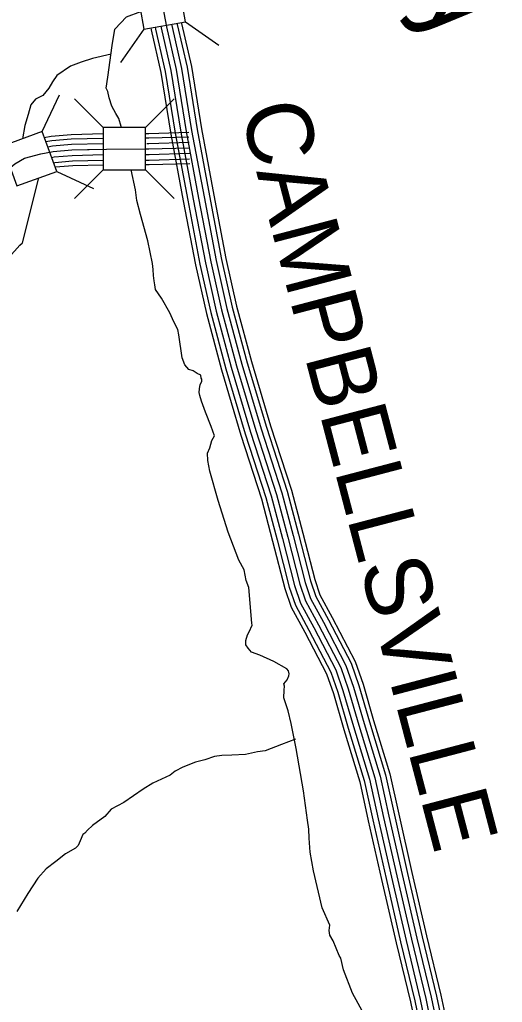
# Model space of a CAD drawing. Extents: x 1551132 to 1791609, y 378168 to 563823.
# Drawn here: x 1640452 to 1643158, y 410247 to 415751 of the extents above; entities that cross this region are included whole.
import ezdxf

# ---------------------------------------------------------------- set-up
doc = ezdxf.new("R2010")
doc.units = 0
for name, color, linetype in [('DESIGN - DRAINAGE - Bridges and Cross Drains Size Text', 7, 'Continuous'), ('DESIGN - ROW - Right-of-Way and Easement Labels', 7, 'Continuous'), ('DESIGN - TRANSPORTATION - Text', 7, 'Continuous'), ('SURVEY - CONTROL with Text', 7, 'Continuous'), ('SURVEY - DRAINAGE - Storm Sewer', 7, 'Continuous'), ('SURVEY - PROPERTY - Owners', 7, 'Continuous'), ('SURVEY - TRANSPORTATION - Roads', 7, 'Continuous')]:
    doc.layers.add(name, color=color, linetype=linetype)

msp = doc.modelspace()

# ---------------------------------------------------------------- linework, layer by layer
at = {"layer": 'DESIGN - TRANSPORTATION - Text'}
for points in [[(1641023.022, 415147.463), (1641021.68, 415152.822), (1641007.972, 415196.99), (1640990.156, 415225.165), (1640968.432, 415267.383), (1640952.74, 415313.568), (1640946.974, 415349.669), (1640937.091, 415367.769), (1640945.499, 415429.812), (1640970.665, 415605.859), (1640985.34, 415698.794), (1641051.355, 415767.28), (1641130.428, 415797.93)], [(1640963.965, 415558.999), (1640860.643, 415534.632), (1640797.069, 415512.623), (1640735.945, 415490.614), (1640660.147, 415439.254), (1640635.698, 415402.561), (1640616.14, 415368.327), (1640581.907, 415326.743), (1640541.558, 415305.351), (1640514.667, 415274.775), (1640498.768, 415219.748), (1640480.435, 415158.605), (1640466.993, 415083.995)], [(1641736.754, 412571.563), (1641721.004, 412609.73), (1641709.396, 412669.915), (1641679.755, 412724.208), (1641620.782, 412880.887), (1641563.941, 413057.575), (1641517.018, 413222.171), (1641507.418, 413282.34), (1641505.676, 413322.416), (1641517.876, 413352.375), (1641528.151, 413394.376), (1641544.317, 413420.302), (1641524.659, 413472.528), (1641493.185, 413552.88), (1641471.594, 413615.132), (1641461.794, 413645.249), (1641457.911, 413663.308), (1641460.044, 413683.325), (1641464.202, 413707.334), (1641472.319, 413725.31), (1641472.394, 413737.326), (1641468.436, 413743.368), (1641466.544, 413759.402), (1641446.611, 413769.561), (1641424.703, 413783.744), (1641400.754, 413791.92), (1641388.838, 413804.028), (1641376.93, 413818.137), (1641363.18, 413856.296), (1641344.03, 413986.641), (1641338.231, 414016.734), (1641316.506, 414058.952), (1641292.84, 414109.203), (1641247.383, 414191.663), (1641213.7, 414239.973), (1641209.867, 414266.049), (1641206.009, 414288.108), (1641202.209, 414318.183), (1641200.434, 414352.251), (1641196.659, 414386.335), (1641169.485, 414512.73), (1641128.444, 414659.259), (1641108.961, 414737.528), (1641101.353, 414797.679), (1641077.462, 414909.799)], [(1640344.571, 414366.659), (1640453.368, 414488.087), (1640467.726, 414501.746), (1640559.258, 414864.739)], [(1642392.262, 410162.866), (1642317.147, 410297.62), (1642267.998, 410428.182), (1642252.441, 410494.4), (1642242.532, 410508.492), (1642209.067, 410590.861), (1642191.284, 410623.037), (1642187.45, 410649.112), (1642189.65, 410679.146), (1642148.285, 410775.591), (1642099.653, 410984.279), (1642080.337, 411088.582), (1642074.845, 411166.751), (1642073.17, 411216.844), (1642065.504, 411266.979), (1642042.579, 411431.408), (1642002.13, 411668.081), (1641973.056, 411808.518), (1641957.523, 411880.745), (1641931.999, 411953.038), (1641934.274, 411995.089), (1641936.424, 412017.115), (1641932.516, 412031.165), (1641950.657, 412053.074), (1641960.798, 412075.033), (1641962.873, 412087.042), (1641958.982, 412103.092), (1641949.065, 412115.184), (1641877.334, 412155.76), (1641797.577, 412192.378), (1641751.678, 412208.728), (1641731.829, 412230.912), (1641719.946, 412249.021), (1641720.104, 412273.063), (1641728.312, 412305.056), (1641738.429, 412323.014), (1641754.662, 412358.957), (1641752.945, 412371.624), (1641736.754, 412571.563)], [(1641998.855, 411720.199), (1641918.974, 411690.84), (1641828.751, 411655.414), (1641784.71, 411649.722), (1641718.629, 411636.163), (1641640.589, 411630.713), (1641584.582, 411629.104), (1641544.549, 411623.379), (1641490.434, 411605.729), (1641438.344, 411592.078), (1641366.17, 411564.544), (1641324.03, 411542.81), (1641295.872, 411518.968), (1641197.591, 411475.592), (1641143.375, 411441.924), (1641034.886, 411366.564), (1640964.638, 411329.005), (1640928.364, 411287.195), (1640860.049, 411237.594), (1640831.874, 411211.751), (1640817.758, 411193.826), (1640805.725, 411187.901), (1640791.483, 411151.941), (1640779.317, 411125.982), (1640765.217, 411110.057), (1640709.01, 411078.406), (1640654.737, 411036.722), (1640600.463, 410995.037), (1640554.131, 410943.277), (1640497.565, 410857.542), (1640436.908, 410755.806)]]:
    msp.add_lwpolyline(points, dxfattribs=at)
at = {"layer": 'SURVEY - CONTROL with Text'}
for points in [[(1641235.834, 415918.325), (1641274.641, 415711.637), (1641329.282, 415472.772), (1641385.263, 415125.663), (1641455.112, 414752.412), (1641523.06, 414395.21), (1641583.525, 414126.245), (1641667.756, 413813.037), (1641775.72, 413449.586), (1641891.734, 413092.085), (1641954.382, 412853.179), (1642022.897, 412590.18), (1642054.371, 412495.786), (1642127.669, 412361.041), (1642252.408, 412121.759), (1642293.757, 412003.248), (1642352.622, 411800.443), (1642442.97, 411505.243), (1642491.702, 411282.454), (1642565.833, 410955.279), (1642647.806, 410599.995), (1642727.929, 410268.778), (1642766.853, 410082.123)], [(1641186.652, 415704.936), (1641188.752, 415693.753), (1641243.142, 415455.988), (1641298.84, 415110.613), (1641368.922, 414736.144), (1641437.162, 414377.385), (1641498.344, 414105.228), (1641583.35, 413789.153), (1641691.947, 413423.552), (1641807.527, 413067.401), (1641869.517, 412830.995), (1641938.757, 412565.221), (1641973.615, 412460.677), (1642050.246, 412319.806), (1642171.685, 412086.85), (1642210.167, 411976.556), (1642268.566, 411775.375), (1642358.047, 411483.001), (1642406.087, 411263.387), (1642480.327, 410935.728), (1642562.442, 410579.819), (1642642.348, 410249.502), (1642681.73, 410060.647)], [(1641211.968, 415709.445), (1641213.934, 415698.995), (1641268.391, 415460.913), (1641324.181, 415115.021), (1641394.188, 414740.911), (1641462.345, 414382.61), (1641523.318, 414111.386), (1641608.091, 413796.153), (1641716.513, 413431.185), (1641832.21, 413074.634), (1641894.4, 412837.503), (1641963.423, 412572.538), (1641997.289, 412470.968), (1642072.946, 412331.89), (1642195.351, 412097.084), (1642234.675, 411984.381), (1642293.207, 411782.726), (1642382.946, 411489.518), (1642431.187, 411268.979), (1642505.393, 410941.462), (1642587.466, 410585.736), (1642667.439, 410255.152), (1642706.688, 410066.939)], [(1641242.5, 415714.812), (1641244.284, 415705.32), (1641298.841, 415466.839), (1641354.722, 415120.346), (1641424.654, 414746.661), (1641492.702, 414388.91), (1641553.426, 414118.82), (1641637.923, 413804.595), (1641746.112, 413440.386), (1641861.976, 413083.36), (1641924.391, 412845.337), (1641993.164, 412581.363), (1642025.83, 412483.377), (1642100.312, 412346.465), (1642223.884, 412109.426), (1642264.216, 411993.814), (1642322.915, 411791.584), (1642412.954, 411497.385), (1642461.444, 411275.712), (1642535.617, 410948.37), (1642617.64, 410592.861), (1642697.68, 410261.969), (1642736.771, 410074.531)], [(1641273.033, 415720.212), (1641274.641, 415711.637), (1641329.282, 415472.772), (1641385.263, 415125.663), (1641455.112, 414752.412), (1641523.06, 414395.21), (1641583.525, 414126.245), (1641667.756, 413813.037), (1641775.72, 413449.586), (1641891.734, 413092.085), (1641954.382, 412853.179), (1642022.897, 412590.18), (1642054.371, 412495.786), (1642127.669, 412361.041), (1642252.408, 412121.759), (1642293.757, 412003.248), (1642352.622, 411800.443), (1642442.97, 411505.243), (1642491.702, 411282.454), (1642565.833, 410955.279), (1642647.806, 410599.995), (1642727.929, 410268.778), (1642766.853, 410082.123)], [(1641303.557, 415725.629), (1641304.999, 415717.953), (1641359.723, 415478.706), (1641415.804, 415130.98), (1641485.569, 414758.162), (1641553.417, 414401.511), (1641613.624, 414133.67), (1641697.589, 413821.479), (1641805.328, 413458.786), (1641921.491, 413100.81), (1641984.373, 412861.02), (1642052.63, 412598.997), (1642082.912, 412508.195), (1642155.027, 412375.616), (1642280.932, 412134.093), (1642323.298, 412012.682), (1642382.33, 411809.301), (1642472.986, 411513.102), (1642521.96, 411289.196), (1642596.049, 410962.187), (1642677.972, 410607.128), (1642758.179, 410275.586), (1642796.936, 410089.715)], [(1641334.09, 415730.962), (1641335.348, 415724.279), (1641390.172, 415484.631), (1641446.345, 415136.305), (1641516.035, 414763.912), (1641583.775, 414407.811), (1641643.732, 414141.104), (1641727.421, 413829.921), (1641834.927, 413467.986), (1641951.257, 413109.535), (1642014.364, 412868.854), (1642082.371, 412607.822), (1642111.453, 412520.603), (1642182.393, 412390.191), (1642309.465, 412146.435), (1642352.839, 412022.115), (1642412.038, 411818.16), (1642502.994, 411520.969), (1642552.217, 411295.93), (1642626.274, 410969.096), (1642708.147, 410614.253), (1642788.42, 410282.403), (1642827.019, 410097.306)], [(1641358.431, 415735.296), (1641359.556, 415729.312), (1641414.438, 415489.364), (1641470.695, 415140.547), (1641540.326, 414768.487), (1641607.974, 414412.828), (1641667.731, 414147.029), (1641751.204, 413836.646), (1641858.535, 413475.32), (1641974.982, 413116.485), (1642038.28, 412875.112), (1642106.078, 412614.856), (1642134.211, 412530.495), (1642204.209, 412401.808), (1642332.206, 412156.269), (1642376.388, 412029.64), (1642435.72, 411825.218), (1642526.926, 411527.236), (1642576.342, 411301.305), (1642650.365, 410974.613), (1642732.196, 410619.937), (1642812.536, 410287.828), (1642851.001, 410103.357)]]:
    msp.add_lwpolyline(points, dxfattribs=at)
at = {"layer": 'SURVEY - DRAINAGE - Storm Sewer'}
for p, q in [((1641381.961, 415739.435), (1641568.007, 415609.164)), ((1641148.02, 415698.179), (1641017.758, 415512.125)), ((1640578.53, 415124.585), (1640674.517, 415330.447)), ((1640919.885, 415147.816), (1640759.28, 415308.412)), ((1641157.477, 415147.822), (1641318.073, 415308.434)), ((1640659.761, 414901.312), (1640865.605, 414805.325)), ((1640919.891, 414910.232), (1640759.286, 414749.619)), ((1641157.441, 414910.238), (1641318.046, 414749.641))]:
    msp.add_line(p, q, dxfattribs=at)
for points in [[(1641148.02, 415698.179), (1641382.003, 415739.435), (1641340.739, 415973.417), (1641106.756, 415932.162)], [(1640436.529, 414820.073), (1640659.803, 414901.337), (1640578.53, 415124.585), (1640355.265, 415043.33)], [(1640919.891, 414910.232), (1641157.483, 414910.238), (1641157.477, 415147.822), (1640919.885, 415147.816)]]:
    msp.add_lwpolyline(points, close=True, dxfattribs=at)
at = {"layer": 'SURVEY - PROPERTY - Owners'}
msp.add_lwpolyline([(1639573.914, 414056.642), (1639626.487, 414119.694), (1639888.506, 414412.06), (1640021.603, 414571.239), (1640106.168, 414652.7), (1640200.849, 414752.102), (1640319.572, 414857.322), (1640424.169, 414944.633), (1640478.385, 414976.259), (1640570.532, 414999.584), (1640640.606, 415013.068), (1640744.653, 415022.285), (1640938.64, 415026.802), (1641176.593, 415026.985), (1641402.446, 415033.861)], dxfattribs=at)
at = {"layer": 'SURVEY - TRANSPORTATION - Roads'}
for points in [[(1640590.157, 415091.67), (1640628.556, 415099.062), (1640739.812, 415108.912), (1640919.866, 415113.104)], [(1641157.477, 415113.688), (1641175.243, 415113.704), (1641399.805, 415120.538)], [(1641157.477, 415088.97), (1641175.627, 415088.987), (1641400.563, 415095.837)], [(1640598.873, 415068.178), (1640631.989, 415074.553), (1640741.195, 415084.22), (1640919.883, 415088.387)], [(1640609.69, 415038.694), (1640636.298, 415043.81), (1640742.92, 415053.252), (1640919.866, 415057.378)], [(1641165.085, 415057.978), (1641176.11, 415057.986), (1641401.505, 415064.845)], [(1640620.348, 415009.168), (1640640.606, 415013.068), (1640744.653, 415022.285), (1640920.008, 415026.368)], [(1640631.139, 414979.675), (1640644.914, 414982.325), (1640746.387, 414991.317), (1640919.874, 414995.359)], [(1641157.477, 415026.969), (1641176.593, 415026.985), (1641402.446, 415033.861)], [(1641157.477, 414995.968), (1641177.077, 414995.984), (1641403.388, 415002.876)], [(1640642.047, 414950.2), (1640649.222, 414951.583), (1640748.112, 414960.35), (1640919.908, 414964.35)], [(1640650.555, 414925.649), (1640652.797, 414926.082), (1640749.545, 414934.658), (1640919.841, 414938.624)], [(1641157.477, 414964.967), (1641177.56, 414964.984), (1641404.33, 414971.884)], [(1641157.477, 414939.25), (1641177.96, 414939.266), (1641405.113, 414946.183)]]:
    msp.add_lwpolyline(points, dxfattribs=at)

# ---------------------------------------------------------------- texts
at = {"layer": 'DESIGN - DRAINAGE - Bridges and Cross Drains Size Text'}
msp.add_text('Wiley', height=475.0017, rotation=311.830728, dxfattribs=at).set_placement((1641851.078, 416774.048))
at = {"layer": 'DESIGN - ROW - Right-of-Way and Easement Labels'}
msp.add_text('CAMPBELLSVILLE', height=370.00844, rotation=284.694208, dxfattribs=at).set_placement((1641686.256, 415247.541))

doc.saveas('drawing.dxf')
